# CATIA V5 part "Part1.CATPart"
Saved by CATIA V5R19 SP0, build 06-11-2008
Part number: Part1
Source: Unknown
Bounding box of the stored display mesh (mm): x -31 to 31, y -31 to 31, z 0 to 20
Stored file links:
  C:\Users\jsmid\Desktop\DP_Smidak_Forma LEGO\Part1.CATPart
  C:\Users\jsmid\Desktop\Forma_kostka\DOC219.CATPart
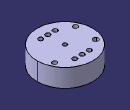
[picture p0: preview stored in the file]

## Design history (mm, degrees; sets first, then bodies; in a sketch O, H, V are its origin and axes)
Body1 (main body)
  Solid1 "PartBody": solid without history
  DatumCurve1 to DatumCurve6
  Sketch1 on face of Solid1, origin (0, 0, 0), H (1, 0, 0), V (0, -1, 0)
    circle A1 centre (0, 18.939) radius 2.25
    point P1 (0, 18.939)
    reference projected circle E1 centre (0, 18.939) radius 2.25 from edge of DatumCurve2
    circle A2 centre (-8.04, 18.939) radius 2.25
    reference projected circle E2 centre (-8.04, 18.939) radius 2.25 from edge of DatumCurve3
    circle A3 centre (8.04, 18.939) radius 2.25
    reference projected circle E3 centre (8.04, 18.939) radius 2.25 from edge of DatumCurve6
    distance A1 E1 = 0
    distance A2 E2 = 0
    radius A1 = 2.25
    radius A2 = 2.25
    distance A3 E3 = 0
    radius A3 = 2.25
    coincidence: P1 V
  Pocket1: profile Sketch1, direction (0, 0, 1), through (limit type 6)
  Mirror1: of Pocket1, about zx-plane
  DatumCurve7 to DatumCurve9
  Sketch2 on face of Solid1, origin (0, 0, 0), H (1, 0, 0), V (0, -1, 0)
    circle A1 centre (0, 18.939) radius 2.5
    point P1 (0, 18.939)
    reference projected circle E1 centre (0, 18.939) radius 2.25 from edge of DatumCurve7
    circle A2 centre (8.04, 18.939) radius 2.5
    reference projected circle E2 centre (8.04, 18.939) radius 2.25 from edge of DatumCurve8
    circle A3 centre (-8.04, 18.939) radius 2.5
    reference projected circle E3 centre (-8.04, 18.939) radius 2.25 from edge of DatumCurve9
    distance A1 E1 = 0.25
    radius A1 = 2.5
    radius A2 = 2.5
    distance A2 E2 = 0.25
    radius A3 = 2.5
    distance A3 E3 = 0.25
    coincidence: P1 V
  Pocket2: profile Sketch2, direction (0, 0, 1), through (limit type 6)
  Mirror2: of Pocket2, about zx-plane
  Sketch3 on face of Solid1, origin (0, 0, 20), H (1, 0, 0), V (0, 1, 0)
    circle A1 centre (0, 0) radius 2.25
    radius A1 = 2.25
  Pocket3: profile Sketch3, direction (0, 0, -1), through (limit type 6)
